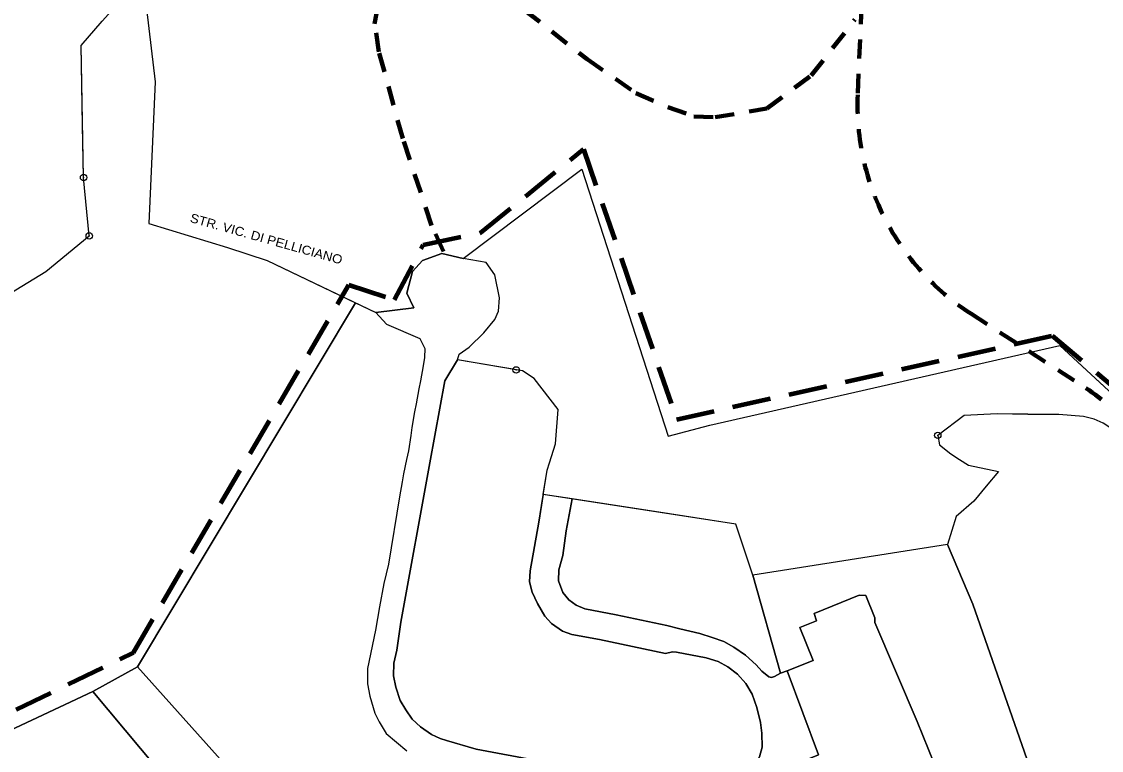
# Model space of a CAD drawing. Extents: x 654952 to 658955, y 890426 to 894481.
# Drawn here: x 657292 to 657629.2, y 891688.7 to 891916.2 of the extents above; entities that cross this region are included whole.
import ezdxf

# ---------------------------------------------------------------- set-up
doc = ezdxf.new("R2010")
doc.units = 0
doc.header["$LTSCALE"] = 4
doc.header["$PDMODE"] = 32
doc.header["$PDSIZE"] = 2
doc.linetypes.add('MEDIUM_DASHED', pattern=[4.5, 3, -1.5])
doc.linetypes.add('SHORT_DASHED', pattern=[2.7, 1.5, -1.2])
for name, color, linetype, lineweight in [('14', 7, 'Continuous', 25), ('19', 7, 'Continuous', 25), ('32', 7, 'Continuous', 25), ('33', 7, 'Continuous', 25), ('35', 7, 'Continuous', 25), ('36', 7, 'Continuous', 25), ('41', 7, 'SHORT_DASHED', 80), ('5', 7, 'Continuous', 25), ('7', 7, 'MEDIUM_DASHED', 100), ('9', 7, 'Continuous', 25)]:
    doc.layers.add(name, color=color, linetype=linetype, lineweight=lineweight)
doc.layers.add('58', color=7, linetype='Continuous')

msp = doc.modelspace()

# ---------------------------------------------------------------- linework, layer by layer
at = {"layer": '14'}
msp.add_lwpolyline([(657607.43, 891681.63), (657589.08, 891734.34), (657581.13, 891753.01), (657520.36, 891743.38), (657529.05, 891712.8), (657531.06, 891713.58), (657539.24, 891716.78), (657535.01, 891727.06), (657540.24, 891729.21), (657539.55, 891731.48), (657553.52, 891737.12), (657555.63, 891737.11), (657558.5, 891730.13), (657558.49, 891728.67), (657571.63, 891697.78), (657578.7, 891680.26)], dxfattribs=at)
at = {"layer": '19'}
for points in [[(657429.9, 891842.26), (657466.92, 891870.18), (657493.96, 891786.85), (657506.91, 891790.22), (657616.23, 891815.12)], [(657629.79, 891790.88), (657626.92, 891792.11), (657623.58, 891792.92), (657615.9, 891793.62), (657596.64, 891793.76), (657586.36, 891793.28), (657578.11, 891787.06), (657578.61, 891784.11), (657582.17, 891781.28), (657584.94, 891779.5), (657587.7, 891777.72), (657597.04, 891775.75), (657593.2, 891771.15), (657589.35, 891766.55), (657583.84, 891761.75), (657581.13, 891753.01), (657520.36, 891743.38), (657515.04, 891759.33), (657454.95, 891768.65), (657456.19, 891776.21), (657456.88, 891778.44), (657458.73, 891784.38), (657459.54, 891795.17), (657452.07, 891804.82), (657448.49, 891807.22), (657428.1, 891810.67), (657428.62, 891812.43), (657431.82, 891814.61), (657436.42, 891819.08), (657439.81, 891823.28), (657440.91, 891825.81), (657441.3, 891830), (657439.82, 891837.13), (657437.13, 891841.04), (657429.9, 891842.26)], [(657616.23, 891815.12), (657638.47, 891794.53)]]:
    msp.add_lwpolyline(points, dxfattribs=at)
at = {"layer": '32'}
msp.add_lwpolyline([(657330.48, 891924.75), (657333.71, 891897.41), (657331.73, 891853.22), (657356.3, 891845.74), (657368.76, 891841.68), (657402.61, 891825.37), (657414.53, 891826.87), (657412.33, 891831.41), (657414.11, 891838.17), (657417.22, 891841.66), (657423.3, 891843.85), (657429.9, 891842.26), (657466.92, 891870.18), (657493.97, 891786.85), (657506.91, 891790.22), (657616.23, 891815.12), (657652.23, 891781.79)], dxfattribs=at)
at = {"layer": '33'}
for points in [[(657383.9, 891623.88), (657314.28, 891707.1), (657328.24, 891714.82), (657363.97, 891674.93)], [(657241.81, 891673.31), (657284.74, 891693.22), (657314.28, 891707.1), (657383.9, 891623.88), (657394.8, 891638.71)]]:
    msp.add_lwpolyline(points, dxfattribs=at)
at = {"layer": '35'}
msp.add_lwpolyline([(657333.71, 891897.41), (657331.73, 891853.22), (657356.3, 891845.74), (657368.76, 891841.68), (657396.27, 891828.43), (657328.24, 891714.82), (657314.28, 891707.1), (657284.74, 891693.21), (657234.36, 891722), (657211.1, 891732.13), (657198.81, 891740.15), (657211.6, 891767.49), (657221.37, 891781.04), (657236.78, 891798.07), (657250.85, 891807.99), (657281.25, 891827.07), (657299.59, 891838.23), (657313.17, 891849.32), (657311.41, 891867.55), (657311.06, 891883.8), (657310.62, 891908.79), (657317.2, 891916.42), (657327.2, 891927.48), (657330.48, 891924.75)], close=True, dxfattribs=at)
at = {"layer": '36'}
for p, q in [((657311.41, 891867.55), (657310.62, 891908.79)), ((657313.17, 891849.32), (657311.41, 891867.55))]:
    msp.add_line(p, q, dxfattribs=at)
for points in [[(657310.62, 891908.79), (657317.2, 891916.42), (657327.2, 891927.48), (657321.01, 891936.2)], [(657246.29, 891488.05), (657247.07, 891495.86), (657154.56, 891651.34), (657241.81, 891673.31), (657284.74, 891693.21), (657234.36, 891722), (657211.1, 891732.13), (657198.81, 891740.15), (657211.6, 891767.49), (657221.37, 891781.04), (657236.78, 891798.07), (657250.85, 891807.99), (657281.25, 891827.07), (657299.59, 891838.23), (657313.17, 891849.32)]]:
    msp.add_lwpolyline(points, dxfattribs=at)
for p in [(657311.41, 891867.55), (657313.17, 891849.32)]:
    msp.add_point(p, dxfattribs=at)
at = {"layer": '41'}
for p, q in [((657555.25, 891943.05), (657553.12, 891893.42)), ((657588.44, 891825.06), (657624.35, 891801.83))]:
    msp.add_line(p, q, dxfattribs=at)
msp.add_lwpolyline([(657423.73, 891844.49), (657420.07, 891852.62), (657411.04, 891879.73), (657403.6, 891906.76), (657402.28, 891915.56), (657404.14, 891925.22), (657405.93, 891928.5), (657408.66, 891932.36), (657415.4, 891935.36), (657419.68, 891936.02), (657426, 891934.67), (657432.83, 891931.25), (657449.12, 891919.85), (657468.6, 891904.5), (657483.88, 891893.88), (657493.84, 891889.55), (657501.99, 891886.66), (657508.61, 891886.39), (657524.72, 891889.08), (657538.62, 891899.4), (657552.24, 891916.91)], dxfattribs=at)
for centre, radius, start, end in [((657630.51, 891890.1), 77.46, 177.5456, 237.1028), ((657593.96, 891754.86), 55.94, 17.7593, 57.1028)]:
    msp.add_arc(centre, radius, start, end, dxfattribs=at)
at = {"layer": '5'}
for points in [[(657429.9, 891842.26), (657423.3, 891843.85), (657417.22, 891841.66), (657414.11, 891838.17), (657412.33, 891831.41), (657414.53, 891826.87), (657402.62, 891825.37), (657405.97, 891821.81), (657416.38, 891817.27), (657417.96, 891814.14), (657417.87, 891811.36), (657417.39, 891808.81), (657416.59, 891804.11), (657416.11, 891801.55), (657415.24, 891796.92), (657414.73, 891794.39), (657413.92, 891789.54), (657413.54, 891787.05), (657412.8, 891782.2), (657412.23, 891779.56), (657411.32, 891775.06), (657410.91, 891772.52), (657410.02, 891767.91), (657406.56, 891746.82), (657405.16, 891740.78), (657403.84, 891733.54), (657402.53, 891726.29), (657400.1, 891714.31), (657400, 891709.53), (657400.83, 891705.69), (657402.39, 891700.3), (657403.71, 891697.66), (657405.83, 891693.98), (657412.36, 891688.52)], [(657428.1, 891810.67), (657428.62, 891812.43), (657431.82, 891814.61), (657436.42, 891819.08), (657439.81, 891823.28), (657440.91, 891825.81), (657441.3, 891830), (657439.82, 891837.13), (657437.13, 891841.04), (657429.9, 891842.26)], [(657424.67, 891691.78), (657422.69, 891692.44), (657420.03, 891693.69), (657416.55, 891696.07), (657414.04, 891698.48), (657411.99, 891701.34), (657410.21, 891704.31), (657408.92, 891708.47), (657408.22, 891712.03), (657408.32, 891715.99), (657409.21, 891719.99), (657410.48, 891728.78), (657419.5, 891778.44), (657424.16, 891804.05), (657428.1, 891810.67)], [(657454.95, 891768.65), (657453.52, 891759.95), (657450.86, 891744.82), (657450.65, 891741.32), (657451.43, 891738.12), (657453.17, 891734.62), (657455.38, 891730.6), (657457.51, 891728.3), (657460.91, 891725.91), (657463.84, 891724.94), (657472.46, 891723.33), (657493.05, 891718.92)], [(657477.7, 891731.07), (657467.94, 891732.92), (657465.24, 891734), (657462.88, 891735.7), (657461.09, 891738.03), (657459.68, 891741.6), (657459.78, 891745.09), (657461.08, 891749.58), (657462.11, 891757.23), (657463.91, 891767.26), (657454.95, 891768.65)], [(657527.09, 891711.76), (657526.2, 891711.44), (657525.37, 891711.68), (657523.22, 891713.4), (657521.44, 891715.42), (657518.07, 891718.49), (657514.47, 891720.9), (657511.28, 891722.71), (657507.67, 891723.99), (657503.83, 891725.19), (657497.57, 891726.67), (657493.53, 891727.67), (657477.7, 891731.07)], [(657493.05, 891718.92), (657495.32, 891719.49), (657496.49, 891719.4), (657505.82, 891717.61), (657509.57, 891716.5), (657512.54, 891714.77), (657515.53, 891712.53), (657518.22, 891709.64), (657520.12, 891706.27), (657521.62, 891702.13), (657522.77, 891697.46), (657523.2, 891694.06), (657523.25, 891689.69), (657522.48, 891686.72), (657521.17, 891684.28), (657518.74, 891681.53), (657515.54, 891678.84), (657512.03, 891677.11), (657501.45, 891677.37), (657495.69, 891677.51), (657434, 891689.06), (657424.67, 891691.78)], [(657562.94, 891600.94), (657558.81, 891608.09), (657556.51, 891614.85), (657553.98, 891622.1), (657551.38, 891629.84), (657550.35, 891632.65), (657550.4, 891634.52), (657550.74, 891635.6), (657548.69, 891642.72), (657542.89, 891660), (657542.44, 891661.57), (657534.68, 891684.82), (657540.84, 891687.29), (657531.06, 891713.58), (657529.05, 891712.8), (657527.09, 891711.76)]]:
    msp.add_lwpolyline(points, dxfattribs=at)
at = {"layer": '7'}
for points in [[(657326.96, 891719.28), (657394.25, 891834.07), (657408.5, 891829.37), (657417.46, 891846.55), (657435.38, 891850.29), (657467.48, 891876.44), (657496.6, 891792.02), (657613.82, 891818.17), (657654.89, 891783.8), (657785.69, 891844.55), (657765.39, 891878.68), (657740.75, 891907.82), (657660.12, 891878.68), (657658.62, 891957.13)], [(657758.18, 891086.01), (657767.85, 891164.67), (657775.55, 891223.85), (657822.54, 891222.57), (657837.5, 891231.12), (657880.22, 891296.95), (657771.27, 891351.67), (657796.48, 891282.84), (657785.37, 891273.87), (657645.7, 891279.64), (657577.41, 891223.2), (657525.69, 891246.07), (657466.47, 891318.42), (657388.34, 891335.24), (657356.54, 891378.41), (657379.71, 891383.41), (657362.45, 891431.59), (657340.55, 891496.17), (657245.72, 891490.19), (657147.58, 891653.01), (657241.87, 891677.78), (657326.96, 891719.28)]]:
    msp.add_lwpolyline(points, dxfattribs=at)
at = {"layer": '9'}
for points in [[(657363.97, 891674.93), (657328.24, 891714.82), (657396.27, 891828.43), (657402.61, 891825.38), (657405.97, 891821.81), (657416.38, 891817.27), (657417.96, 891814.14), (657417.87, 891811.36), (657417.39, 891808.81), (657416.59, 891804.11), (657416.11, 891801.55), (657415.24, 891796.92), (657414.73, 891794.39), (657413.92, 891789.54), (657413.54, 891787.05), (657412.8, 891782.2), (657412.23, 891779.56), (657411.32, 891775.06), (657410.91, 891772.52), (657410.02, 891767.91), (657406.56, 891746.82), (657405.16, 891740.78), (657403.84, 891733.54), (657402.53, 891726.29), (657400.1, 891714.31), (657400, 891709.53), (657400.83, 891705.69), (657402.39, 891700.3), (657403.71, 891697.66), (657405.83, 891693.98), (657412.36, 891688.52)], [(657446.44, 891807.49), (657428.1, 891810.67), (657424.16, 891804.05), (657419.5, 891778.44), (657410.48, 891728.78), (657409.21, 891719.99)], [(657493.05, 891718.92), (657472.46, 891723.33), (657463.84, 891724.94), (657460.91, 891725.91), (657457.51, 891728.3), (657455.38, 891730.6), (657453.17, 891734.62), (657451.43, 891738.12), (657450.65, 891741.32), (657450.86, 891744.82), (657453.52, 891759.95), (657456.19, 891776.21), (657456.88, 891778.44), (657458.73, 891784.38), (657459.54, 891795.17), (657452.07, 891804.82), (657448.49, 891807.22), (657446.44, 891807.49)], [(657638.07, 891778.7), (657636.17, 891783.28), (657633.5, 891787.83), (657631.83, 891789.56), (657629.79, 891790.88), (657626.92, 891792.11), (657623.58, 891792.92), (657615.9, 891793.62), (657606.21, 891793.58), (657596.64, 891793.76), (657586.36, 891793.28), (657578.11, 891787.06)], [(657578.61, 891784.11), (657582.17, 891781.28), (657584.94, 891779.5), (657587.7, 891777.72), (657597.04, 891775.75), (657593.2, 891771.15), (657589.35, 891766.55), (657583.84, 891761.75), (657581.13, 891753.01), (657589.08, 891734.34), (657607.43, 891681.63), (657622.86, 891669.7), (657618.17, 891659.54), (657600.13, 891618.34), (657593.79, 891611.94), (657623.23, 891604.4)], [(657529.05, 891712.8), (657520.36, 891743.38), (657515.04, 891759.33), (657491.06, 891763.12), (657463.91, 891767.28), (657462.11, 891757.23), (657461.08, 891749.58)], [(657461.08, 891749.58), (657459.78, 891745.09), (657459.68, 891741.6), (657461.09, 891738.03), (657462.88, 891735.7), (657465.24, 891734), (657467.94, 891732.92), (657477.7, 891731.07)], [(657477.7, 891731.07), (657493.53, 891727.67), (657497.57, 891726.67), (657503.83, 891725.19), (657507.67, 891723.99), (657511.28, 891722.71), (657514.47, 891720.9), (657518.07, 891718.49), (657521.44, 891715.42), (657523.22, 891713.4), (657525.37, 891711.68), (657526.2, 891711.44), (657527.09, 891711.76), (657529.05, 891712.8)], [(657409.21, 891719.99), (657408.32, 891715.99), (657408.22, 891712.03), (657408.92, 891708.47), (657410.21, 891704.31), (657411.99, 891701.34), (657414.04, 891698.48), (657416.55, 891696.07), (657420.03, 891693.69), (657422.69, 891692.44), (657424.67, 891691.78), (657434, 891689.06), (657495.69, 891677.51), (657501.45, 891677.37)], [(657501.45, 891677.37), (657512.03, 891677.11), (657515.54, 891678.84), (657518.74, 891681.53), (657521.17, 891684.28), (657522.48, 891686.72), (657523.25, 891689.69), (657523.2, 891694.06), (657522.77, 891697.46), (657521.62, 891702.13), (657520.12, 891706.27), (657518.22, 891709.64), (657515.53, 891712.53), (657512.54, 891714.77), (657509.57, 891716.5), (657505.82, 891717.61), (657496.49, 891719.4), (657495.32, 891719.49), (657493.05, 891718.92)]]:
    msp.add_lwpolyline(points, dxfattribs=at)
msp.add_lwpolyline([(657534.68, 891684.82), (657542.44, 891661.57), (657542.89, 891660), (657548.69, 891642.72), (657550.74, 891635.6), (657557.15, 891640.89), (657574.82, 891655.41), (657577.58, 891661.44), (657579.45, 891666.01), (657580.58, 891671.95), (657579.86, 891676.86), (657578.7, 891680.26), (657571.63, 891697.78), (657558.49, 891728.67), (657558.5, 891730.13), (657555.63, 891737.11), (657553.52, 891737.12), (657539.55, 891731.48), (657540.24, 891729.21), (657535.01, 891727.06), (657539.24, 891716.78), (657531.06, 891713.58), (657540.84, 891687.29)], close=True, dxfattribs=at)
for p in [(657446.44, 891807.49), (657578.11, 891787.06)]:
    msp.add_point(p, dxfattribs=at)

# ---------------------------------------------------------------- texts
at = {"layer": '58', "width": 1.1}
msp.add_text('STR. VIC. DI PELLICIANO', height=2.8, rotation=344.296, dxfattribs=at).set_placement((657344.4, 891853.73))

doc.saveas('drawing.dxf')
